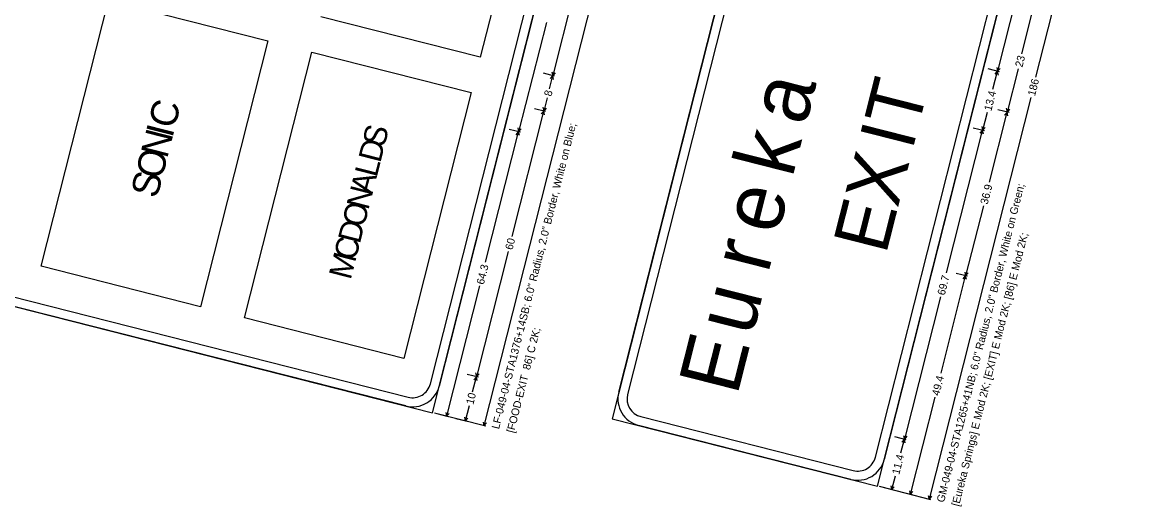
# Model space of a CAD drawing. Extents: x 670257 to 671518, y 737783 to 738188.
# Drawn here: x 670686.95 to 670722.59, y 738022.85 to 738038.31 of the extents above; entities that cross this region are included whole.
import ezdxf

# ---------------------------------------------------------------- set-up
doc = ezdxf.new("R2010")
doc.units = 0
doc.layers.add('R_SIGN', color=7, linetype='Continuous')

msp = doc.modelspace()

# ---------------------------------------------------------------- linework, layer by layer
at = {"layer": 'R_SIGN'}
for p, q in [((670719.339, 738036.563), (670722.591, 738049.385)), ((670703.733, 738045.683), (670701.582, 738037.202)), ((670719.458, 738042.056), (670718.113, 738036.75)), ((670704.916, 738040.616), (670703.901, 738036.613)), ((670705.49, 738040.366), (670701.703, 738025.436)), ((670687.553, 738030.529), (670689.704, 738039.011)), ((670689.704, 738039.011), (670694.793, 738037.72)), ((670701.582, 738037.202), (670696.493, 738038.492)), ((670718.892, 738037.313), (670719.244, 738038.699)), ((670703.696, 738038.313), (670702.81, 738034.822)), ((670694.793, 738037.72), (670692.642, 738029.238)), ((670694.055, 738028.88), (670696.206, 738037.361)), ((670696.206, 738037.361), (670701.295, 738036.071)), ((670703.961, 738036.598), (670703.602, 738036.689)), ((670703.875, 738036.734), (670703.901, 738036.613)), ((670703.982, 738036.707), (670703.901, 738036.613)), ((670718.173, 738036.735), (670717.814, 738036.826)), ((670717.967, 738036.177), (670718.113, 738036.75)), ((670718.032, 738036.657), (670718.113, 738036.75)), ((670718.087, 738036.871), (670718.113, 738036.75)), ((670718.194, 738036.843), (670718.113, 738036.75)), ((670718.139, 738036.629), (670718.113, 738036.75)), ((670718.771, 738036.834), (670718.419, 738035.448)), ((670703.794, 738036.191), (670703.901, 738036.613)), ((670703.821, 738036.52), (670703.901, 738036.613)), ((670703.928, 738036.493), (670703.901, 738036.613)), ((670701.295, 738036.071), (670699.144, 738027.589)), ((670703.588, 738035.603), (670703.614, 738035.483)), ((670703.722, 738035.906), (670703.614, 738035.483)), ((670703.695, 738035.576), (670703.614, 738035.483)), ((670719.175, 738035.916), (670715.923, 738023.093)), ((670718.393, 738035.569), (670718.419, 738035.448)), ((670702.599, 738031.48), (670703.614, 738035.483)), ((670703.674, 738035.467), (670703.315, 738035.558)), ((670703.534, 738035.389), (670703.614, 738035.483)), ((670703.641, 738035.362), (670703.614, 738035.483)), ((670717.78, 738035.438), (670717.635, 738034.865)), ((670717.853, 738033.217), (670718.419, 738035.448)), ((670718.479, 738035.433), (670718.12, 738035.524)), ((670718.339, 738035.355), (670718.419, 738035.448)), ((670718.5, 738035.542), (670718.419, 738035.448)), ((670718.446, 738035.327), (670718.419, 738035.448)), ((670702.87, 738034.806), (670702.511, 738034.897)), ((670702.784, 738034.942), (670702.81, 738034.822)), ((670702.891, 738034.915), (670702.81, 738034.822)), ((670716.482, 738030.318), (670717.635, 738034.865)), ((670717.695, 738034.85), (670717.336, 738034.941)), ((670717.554, 738034.772), (670717.635, 738034.865)), ((670717.608, 738034.986), (670717.635, 738034.865)), ((670717.715, 738034.959), (670717.635, 738034.865)), ((670717.661, 738034.745), (670717.635, 738034.865)), ((670701.755, 738030.663), (670702.81, 738034.822)), ((670702.729, 738034.728), (670702.81, 738034.822)), ((670702.836, 738034.701), (670702.81, 738034.822)), ((670717.66, 738032.455), (670717.094, 738030.223)), ((670702.478, 738031.004), (670701.463, 738027.001)), ((670692.642, 738029.238), (670687.553, 738030.529)), ((670716.307, 738027.12), (670717.094, 738030.223)), ((670717.154, 738030.208), (670716.795, 738030.299)), ((670717.014, 738030.13), (670717.094, 738030.223)), ((670717.068, 738030.344), (670717.094, 738030.223)), ((670717.175, 738030.317), (670717.094, 738030.223)), ((670717.121, 738030.103), (670717.094, 738030.223)), ((670701.561, 738029.898), (670700.506, 738025.739)), ((670716.288, 738029.555), (670715.135, 738025.008)), ((670699.144, 738027.589), (670694.055, 738028.88)), ((670701.523, 738026.986), (670701.164, 738027.077)), ((670701.437, 738027.122), (670701.463, 738027.001)), ((670701.544, 738027.095), (670701.463, 738027.001)), ((670701.341, 738026.52), (670701.463, 738027.001)), ((670701.383, 738026.908), (670701.463, 738027.001)), ((670701.49, 738026.881), (670701.463, 738027.001)), ((670716.111, 738026.348), (670715.324, 738023.245)), ((670701.227, 738026.068), (670701.105, 738025.588)), ((670701.763, 738025.421), (670700.118, 738025.838)), ((670700.566, 738025.724), (670700.207, 738025.815)), ((670700.48, 738025.86), (670700.506, 738025.739)), ((670700.587, 738025.833), (670700.506, 738025.739)), ((670701.165, 738025.572), (670700.806, 738025.663)), ((670701.078, 738025.708), (670701.105, 738025.588)), ((670701.185, 738025.681), (670701.105, 738025.588)), ((670701.677, 738025.556), (670701.703, 738025.436)), ((670701.784, 738025.529), (670701.703, 738025.436)), ((670715.195, 738024.993), (670714.836, 738025.084)), ((670715.024, 738024.571), (670715.135, 738025.008)), ((670715.054, 738024.914), (670715.135, 738025.008)), ((670715.108, 738025.128), (670715.135, 738025.008)), ((670715.215, 738025.101), (670715.135, 738025.008)), ((670715.161, 738024.887), (670715.135, 738025.008)), ((670714.837, 738023.833), (670714.726, 738023.396)), ((670715.982, 738023.078), (670714.337, 738023.495)), ((670714.786, 738023.381), (670714.427, 738023.472)), ((670714.7, 738023.517), (670714.726, 738023.396)), ((670714.807, 738023.49), (670714.726, 738023.396)), ((670715.384, 738023.229), (670715.025, 738023.321)), ((670715.298, 738023.365), (670715.324, 738023.245)), ((670715.405, 738023.338), (670715.324, 738023.245)), ((670715.896, 738023.213), (670715.923, 738023.093)), ((670716.003, 738023.186), (670715.923, 738023.093))]:
    msp.add_line(p, q, dxfattribs=at)
for points in [[(670700.058, 738025.853), (670707.802, 738056.386), (670690.839, 738060.689), (670683.095, 738030.155), (670700.058, 738025.853), (670700.058, 738025.853)], [(670699.99, 738026.773), (670707.304, 738055.61)], [(670707.587, 738055.538), (670700.273, 738026.701)], [(670714.277, 738023.51), (670720.946, 738049.803), (670712.464, 738051.954), (670705.796, 738025.661), (670714.277, 738023.51), (670714.277, 738023.51)], [(670706.011, 738026.509), (670712.249, 738051.106)], [(670712.532, 738051.034), (670706.294, 738026.438)], [(670714.21, 738024.43), (670720.448, 738049.026)], [(670720.731, 738048.955), (670714.492, 738024.358)], [(670684.015, 738030.223), (670699.281, 738026.351)], [(670699.21, 738026.068), (670683.943, 738029.94)], [(670706.716, 738025.729), (670713.501, 738024.008)], [(670713.429, 738023.725), (670706.644, 738025.446)]]:
    msp.add_lwpolyline(points, dxfattribs=at)
for centre, radius, start, end in [((670699.425, 738026.916), 0.875, 255.7684, 345.7686), ((670699.425, 738026.916), 0.583, 255.7684, 345.7686), ((670706.859, 738026.294), 0.875, 165.7688, 255.7684), ((670706.859, 738026.294), 0.583, 165.7688, 255.7684), ((670713.644, 738024.573), 0.875, 255.7684, 345.7686), ((670713.644, 738024.573), 0.583, 255.7684, 345.7686)]:
    msp.add_arc(centre, radius, start, end, dxfattribs=at)

# ---------------------------------------------------------------- texts
for s, height, p in [('23', 0.2469, (670718.906, 738036.864)), ('a', 1.944, (670711.975, 738034.977)), ('T', 1.75, (670715.551, 738034.84)), ('186', 0.2469, (670719.309, 738035.945)), ('8', 0.247, (670703.856, 738035.935)), ('13.4', 0.2469, (670717.915, 738035.468)), ('C', 0.875, (670691.818, 738034.891)), ('N', 0.875, (670691.577, 738033.941)), ('I', 0.875, (670691.745, 738034.602)), ('S', 0.729, (670698.515, 738034.305)), ('LF-049-04-STA1376+14SB; 6.0" Radius, 2.0" Border, White on Blue; ', 0.24688, (670702.182, 738025.314)), ('k', 1.944, (670711.554, 738033.318)), ('I', 1.75, (670715.388, 738034.195)), ('D', 0.729, (670698.388, 738033.803)), ('O', 0.875, (670691.408, 738033.271)), ('X', 1.75, (670714.923, 738032.363)), ('L', 0.729, (670698.272, 738033.343)), ('S', 0.875, (670691.255, 738032.668)), ('N', 0.729, (670698.006, 738032.297)), ('A', 0.729, (670698.132, 738032.792)), ('e', 1.944, (670711.091, 738031.49)), ('GM-049-04-STA1265+41NB; 6.0" Radius, 2.0" Border, White on Green; ', 0.24688, (670716.401, 738022.972)), ('36.9', 0.2469, (670717.795, 738032.484)), ('O', 0.729, (670697.865, 738031.739)), ('E', 1.75, (670714.544, 738030.87)), ('D', 0.729, (670697.732, 738031.216)), ('C', 0.729, (670697.596, 738030.679)), ('60', 0.2469, (670702.613, 738031.034)), ('r', 1.944, (670710.78, 738030.265)), ('[Eureka Springs] E Mod 2K; [EXIT] E Mod 2K; [86] E Mod 2K; ', 0.24688, (670716.88, 738022.85)), ('M', 0.729, (670697.442, 738030.071)), ('64.3', 0.2469, (670701.696, 738029.927)), ('69.7', 0.2469, (670716.423, 738029.584)), ('u', 1.944, (670710.273, 738028.267)), ('[FOOD-EXIT  86] C 2K; ', 0.24688, (670702.66, 738025.193)), ('E', 1.944, (670709.79, 738026.363)), ('49.4', 0.2469, (670716.246, 738026.378)), ('10', 0.2469, (670701.362, 738026.098)), ('11.4', 0.2469, (670714.972, 738023.862))]:
    msp.add_text(s, height=height, rotation=75.7686, dxfattribs=at).set_placement(p)

doc.saveas('drawing.dxf')
